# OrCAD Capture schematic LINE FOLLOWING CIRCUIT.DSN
size A; title: Line following sensor
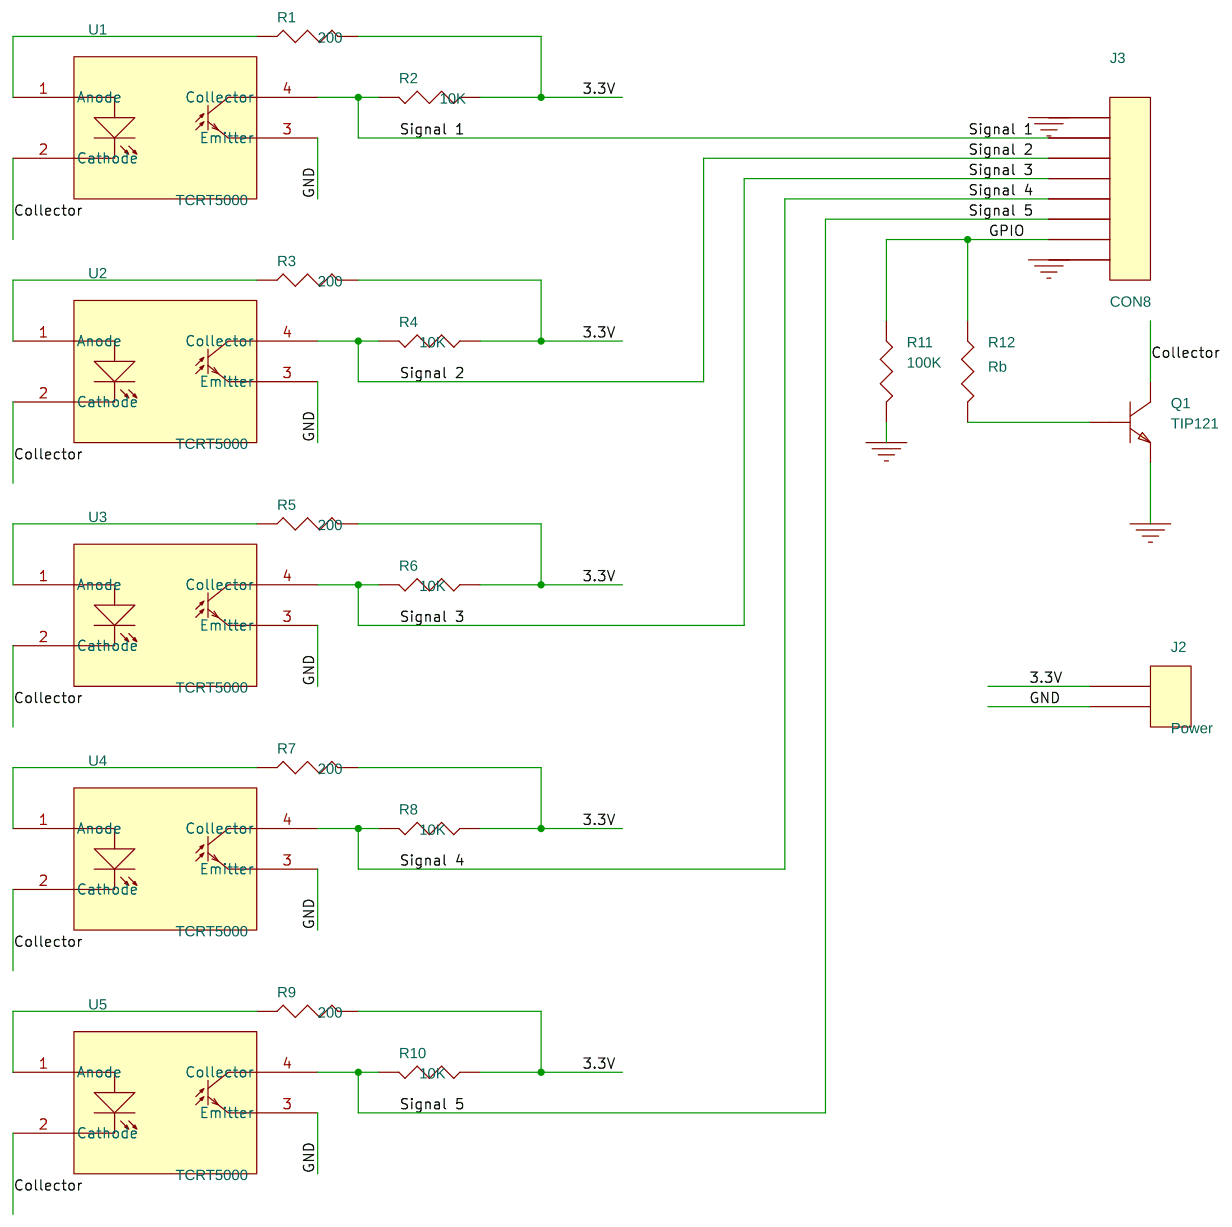
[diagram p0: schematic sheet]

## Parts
J2  Power  [GU-MOLEX2]
J3  CON8  [GU-MOLEX8]
Q1  TIP121  [GU-TO220AB]
R1  200  [GU-RC400]
R2  10K  [GU-RC400]
R3  200  [GU-RC400]
R4  10K  [GU-RC400]
R5  200  [GU-RC400]
R6  10K  [GU-RC400]
R7  200  [GU-RC400]
R8  10K  [GU-RC400]
R9  200  [GU-RC400]
R10  10K  [GU-RC400]
R11  100K  [GU-RC400]
R12  Rb  [GU-RC400]
U1  TCRT5000  [vishay_tcrt5000]
U2  TCRT5000  [vishay_tcrt5000]
U3  TCRT5000  [vishay_tcrt5000]
U4  TCRT5000  [vishay_tcrt5000]
U5  TCRT5000  [vishay_tcrt5000]

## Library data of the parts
J2 = CON2
J3 = CON8
Q1 = 1R1001
R1-R12 = R
U1-U5 = TCRT5000

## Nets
3.3V: J2.1 R1.2 R2.1 R3.2 R4.1 R5.2 R6.1 R7.2 R8.1 R9.2 R10.1
GND: J2.2 J3.1 J3.8 Q1.3(E) R11.2 U1.3(Emitter) U2.3(Emitter) U3.3(Emitter) U4.3(Emitter) U5.3(Emitter)
Collector: Q1.2(C) U1.2(Cathode) U2.2(Cathode) U3.2(Cathode) U4.2(Cathode) U5.2(Cathode)
GPIO: J3.7 R11.1 R12.1
Signal 1: J3.2 R2.2 U1.4(Collector)
Signal 2: J3.3 R4.2 U2.4(Collector)
Signal 3: J3.4 R6.2 U3.4(Collector)
Signal 4: J3.5 R8.2 U4.4(Collector)
Signal 5: J3.6 R10.2 U5.4(Collector)
N08690: R1.1 U1.1(Anode)
N08740: Q1.1(B) R12.2
N09174: R3.1 U2.1(Anode)
N09466: R5.1 U3.1(Anode)
N13033: R7.1 U4.1(Anode)
N13322: R9.1 U5.1(Anode)
